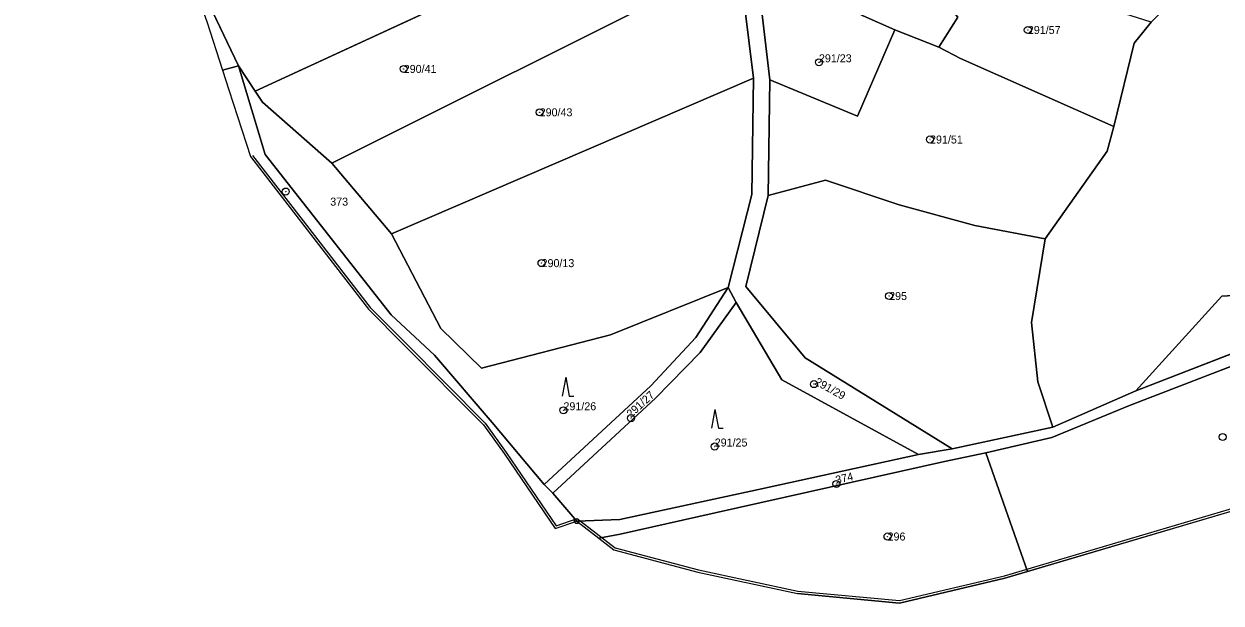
# Model space of a CAD drawing. Extents: x -652854 to -650068, y -1097661 to -1095417.
# Drawn here: x -652329 to -652074.7, y -1097660.5 to -1097537.5 of the extents above; entities that cross this region are included whole.
import ezdxf

# ---------------------------------------------------------------- set-up
doc = ezdxf.new("R2010")
doc.units = 0
for name, color, linetype in [('Definiční body parcel', 7, 'Continuous'), ('Geodetické body', 7, 'Continuous'), ('Hranice obcí', 7, 'Continuous'), ('Hranice parcel', 7, 'Continuous'), ('Obvody jako plochy', 7, 'Continuous'), ('Ostatní hranice', 7, 'Continuous'), ('Parcelní čísla', 7, 'Continuous'), ('Prvky pro prodl_ par_ č_', 7, 'Continuous'), ('Značky kultur', 7, 'Continuous')]:
    doc.layers.add(name, color=color, linetype=linetype)

msp = doc.modelspace()

# ---------------------------------------------------------------- linework, layer by layer
at = {"layer": 'Definiční body parcel'}
for centre, radius in [((-652115.77, -1097538.76), 0.75), ((-652115.77, -1097538.76), 0.0327), ((-652160.15, -1097545.62), 0.75), ((-652248.35, -1097547.03), 0.75), ((-652248.35, -1097547.03), 0.0327), ((-652160.15, -1097545.62), 0.0327), ((-652219.47, -1097556.25), 0.75), ((-652219.47, -1097556.25), 0.0327), ((-652136.55, -1097562.03), 0.75), ((-652136.55, -1097562.03), 0.0327), ((-652273.42, -1097573.09), 0.75), ((-652273.42, -1097573.09), 0.0327), ((-652219.07, -1097588.3), 0.75), ((-652219.07, -1097588.3), 0.0327), ((-652145.24, -1097595.29), 0.75), ((-652145.24, -1097595.29), 0.0327), ((-652161.2, -1097614.01), 0.75), ((-652161.2, -1097614.01), 0.0327), ((-652214.42, -1097619.57), 0.75), ((-652214.42, -1097619.57), 0.0327), ((-652200.08, -1097621.25), 0.75), ((-652200.08, -1097621.25), 0.0327), ((-652182.29, -1097627.27), 0.75), ((-652074.37, -1097625.25), 0.75), ((-652182.29, -1097627.27), 0.0327), ((-652156.43, -1097635.23), 0.75), ((-652156.43, -1097635.23), 0.0327), ((-652145.57, -1097646.4), 0.75), ((-652145.57, -1097646.4), 0.0327)]:
    msp.add_circle(centre, radius, dxfattribs=at)
at = {"layer": 'Geodetické body'}
for radius in [0.5, 0.5, 0.001, 0.001]:
    msp.add_circle((-652211.59, -1097643.14), radius, dxfattribs=at)
at = {"layer": 'Hranice obcí'}
for p, q in [((-652290.21, -1097536.96), (-652286.85, -1097547.32)), ((-652286.85, -1097547.32), (-652285.5, -1097551.5)), ((-652285.5, -1097551.5), (-652280.91, -1097565.66)), ((-652280.91, -1097565.66), (-652270.59, -1097579)), ((-652270.59, -1097579), (-652255.82, -1097598.11)), ((-652255.82, -1097598.11), (-652248.32, -1097605.66)), ((-652248.32, -1097605.66), (-652231.39, -1097622.64)), ((-652231.39, -1097622.64), (-652227.04, -1097628.79)), ((-652227.04, -1097628.79), (-652216.17, -1097644.7)), ((-652068.98, -1097639.97), (-652115.83, -1097653.84)), ((-652216.17, -1097644.7), (-652211.59, -1097643.14)), ((-652211.59, -1097643.14), (-652206.89, -1097646.75)), ((-652206.89, -1097646.75), (-652203.69, -1097649.21)), ((-652203.69, -1097649.21), (-652185.88, -1097653.98)), ((-652185.88, -1097653.98), (-652164.72, -1097658.5)), ((-652115.83, -1097653.84), (-652120.65, -1097655.27)), ((-652120.65, -1097655.27), (-652143.02, -1097660.54)), ((-652143.02, -1097660.54), (-652164.72, -1097658.5))]:
    msp.add_line(p, q, dxfattribs=at)
at = {"layer": 'Hranice parcel'}
for p, q in [((-652279.94, -1097551.79), (-652204.5, -1097516.92)), ((-652170.6, -1097549.34), (-652173.3, -1097526.39)), ((-652291.42, -1097529.59), (-652283.48, -1097546.39)), ((-652263.63, -1097567.04), (-652185.84, -1097528.13)), ((-652174.04, -1097549.02), (-652175.87, -1097534.12)), ((-652150.74, -1097535.77), (-652144.02, -1097538.72)), ((-652134.69, -1097542.44), (-652130.63, -1097536.04)), ((-652089.55, -1097537.12), (-652093.22, -1097541.53)), ((-652144.02, -1097538.72), (-652151.99, -1097557.1)), ((-652134.69, -1097542.44), (-652144.02, -1097538.72)), ((-652130.11, -1097544.83), (-652134.69, -1097542.44)), ((-652093.22, -1097541.53), (-652097.54, -1097559.24)), ((-652130.11, -1097544.83), (-652097.54, -1097559.24)), ((-652283.48, -1097546.39), (-652286.85, -1097547.32)), ((-652283.48, -1097546.39), (-652279.94, -1097551.79)), ((-652283.48, -1097546.39), (-652277.8, -1097565.24)), ((-652250.97, -1097582.05), (-652174.04, -1097549.02)), ((-652174.43, -1097573.73), (-652174.04, -1097549.02)), ((-652170.97, -1097573.93), (-652170.6, -1097549.34)), ((-652151.99, -1097557.1), (-652170.6, -1097549.34)), ((-652279.94, -1097551.79), (-652278.34, -1097554.07)), ((-652278.34, -1097554.07), (-652263.63, -1097567.04)), ((-652097.54, -1097559.24), (-652098.91, -1097564.48)), ((-652277.8, -1097565.24), (-652250.99, -1097599.3)), ((-652098.91, -1097564.48), (-652112.08, -1097583.17)), ((-652263.63, -1097567.04), (-652250.97, -1097582.05)), ((-652158.73, -1097570.67), (-652170.97, -1097573.93)), ((-652143.09, -1097575.93), (-652158.73, -1097570.67)), ((-652179.45, -1097593.46), (-652174.43, -1097573.73)), ((-652175.68, -1097593.25), (-652170.97, -1097573.93)), ((-652127.02, -1097580.3), (-652143.09, -1097575.93)), ((-652112.08, -1097583.17), (-652127.02, -1097580.3)), ((-652250.97, -1097582.05), (-652240.47, -1097602.17)), ((-652112.08, -1097583.17), (-652115.03, -1097600.94)), ((-652204.44, -1097603.55), (-652179.45, -1097593.46)), ((-652186.3, -1097604.08), (-652179.45, -1097593.46)), ((-652179.45, -1097593.46), (-652177.7, -1097596.65)), ((-652163.08, -1097608.43), (-652175.68, -1097593.25)), ((-652092.81, -1097615.42), (-652039.97, -1097594.93)), ((-652074.54, -1097595.34), (-652092.81, -1097615.42)), ((-652177.7, -1097596.65), (-652185.36, -1097607.28)), ((-652177.7, -1097596.65), (-652168.02, -1097613.07)), ((-652250.99, -1097599.3), (-652241.82, -1097607.85)), ((-652115.03, -1097600.94), (-652113.67, -1097613.52)), ((-652240.47, -1097602.17), (-652231.81, -1097610.6)), ((-652231.81, -1097610.6), (-652204.44, -1097603.55)), ((-652195.85, -1097614.41), (-652186.3, -1097604.08)), ((-652241.82, -1097607.85), (-652229.56, -1097622.15)), ((-652185.36, -1097607.28), (-652194.9, -1097616.98)), ((-652131.82, -1097627.74), (-652163.08, -1097608.43)), ((-652066.62, -1097607.96), (-652094.18, -1097618.53)), ((-652168.02, -1097613.07), (-652139.02, -1097628.97)), ((-652113.67, -1097613.52), (-652110.43, -1097623.16)), ((-652218.55, -1097635.33), (-652195.85, -1097614.41)), ((-652110.43, -1097623.16), (-652092.81, -1097615.42)), ((-652194.9, -1097616.98), (-652216.67, -1097637.21)), ((-652094.18, -1097618.53), (-652110.68, -1097625.36)), ((-652229.56, -1097622.15), (-652218.55, -1097635.33)), ((-652131.82, -1097627.74), (-652110.43, -1097623.16)), ((-652110.68, -1097625.36), (-652124.7, -1097628.63)), ((-652172.99, -1097636.38), (-652139.02, -1097628.97)), ((-652139.02, -1097628.97), (-652131.82, -1097627.74)), ((-652124.7, -1097628.63), (-652133.45, -1097630.46)), ((-652124.7, -1097628.63), (-652115.83, -1097653.84)), ((-652133.45, -1097630.46), (-652182.16, -1097641.4)), ((-652218.55, -1097635.33), (-652216.67, -1097637.21)), ((-652202.46, -1097642.79), (-652172.99, -1097636.38)), ((-652216.67, -1097637.21), (-652211.59, -1097643.14)), ((-652182.16, -1097641.4), (-652202.36, -1097645.87)), ((-652211.59, -1097643.14), (-652202.46, -1097642.79)), ((-652202.36, -1097645.87), (-652206.89, -1097646.75))]:
    msp.add_line(p, q, dxfattribs=at)
at = {"layer": 'Obvody jako plochy'}
for points in [[(-652283.48, -1097546.39), (-652291.42, -1097529.59), (-652293.53, -1097523.16), (-652302.62, -1097501.1), (-652308.48, -1097486.7), (-652318.45, -1097463.12), (-652326.36, -1097443.74), (-652329.03, -1097442.14), (-652325.62, -1097450.58), (-652313.01, -1097480.64), (-652302.46, -1097506.84), (-652293.93, -1097526.58), (-652290.21, -1097536.96), (-652286.85, -1097547.32)], [(-652231, -1097501.01), (-652291.42, -1097529.59), (-652283.48, -1097546.39), (-652279.94, -1097551.79), (-652204.5, -1097516.92)], [(-652110.43, -1097623.16), (-652092.81, -1097615.42), (-652074.54, -1097595.34), (-652054.54, -1097594.13), (-652025.66, -1097577.57), (-652014.27, -1097557.8), (-652016.26, -1097555.47), (-652054.38, -1097506.4), (-652060.34, -1097499.52), (-652065.98, -1097508.03), (-652074.75, -1097521.21), (-652081.84, -1097529.25), (-652089.55, -1097537.12), (-652093.22, -1097541.53), (-652097.54, -1097559.24), (-652098.91, -1097564.48), (-652112.08, -1097583.17), (-652115.03, -1097600.94), (-652113.67, -1097613.52)], [(-652204.5, -1097516.92), (-652279.94, -1097551.79), (-652278.34, -1097554.07), (-652263.63, -1097567.04), (-652185.84, -1097528.13)], [(-652150.74, -1097535.77), (-652144.02, -1097538.72), (-652134.69, -1097542.44), (-652130.63, -1097536.04), (-652145.51, -1097518.48), (-652149.63, -1097517.12), (-652158.81, -1097530.29)], [(-652089.55, -1097537.12), (-652119.6, -1097527.55), (-652145.51, -1097518.48), (-652130.63, -1097536.04), (-652134.69, -1097542.44), (-652130.11, -1097544.83), (-652097.54, -1097559.24), (-652093.22, -1097541.53)], [(-652177.7, -1097596.65), (-652168.02, -1097613.07), (-652139.02, -1097628.97), (-652131.82, -1097627.74), (-652163.08, -1097608.43), (-652175.68, -1097593.25), (-652170.97, -1097573.93), (-652170.6, -1097549.34), (-652173.3, -1097526.39), (-652176.77, -1097526.81), (-652175.87, -1097534.12), (-652174.04, -1097549.02), (-652174.43, -1097573.73), (-652179.45, -1097593.46)], [(-652144.02, -1097538.72), (-652150.74, -1097535.77), (-652173.3, -1097526.39), (-652170.6, -1097549.34), (-652151.99, -1097557.1)], [(-652174.04, -1097549.02), (-652175.87, -1097534.12), (-652185.84, -1097528.13), (-652263.63, -1097567.04), (-652250.97, -1097582.05)], [(-652144.02, -1097538.72), (-652151.99, -1097557.1), (-652170.6, -1097549.34), (-652170.97, -1097573.93), (-652158.73, -1097570.67), (-652143.09, -1097575.93), (-652127.02, -1097580.3), (-652112.08, -1097583.17), (-652098.91, -1097564.48), (-652097.54, -1097559.24), (-652130.11, -1097544.83), (-652134.69, -1097542.44)], [(-652229.56, -1097622.15), (-652241.82, -1097607.85), (-652250.99, -1097599.3), (-652277.8, -1097565.24), (-652283.48, -1097546.39), (-652286.85, -1097547.32), (-652285.5, -1097551.5), (-652280.91, -1097565.66), (-652270.59, -1097579), (-652255.82, -1097598.11), (-652248.32, -1097605.66), (-652231.39, -1097622.64), (-652227.04, -1097628.79), (-652216.17, -1097644.7), (-652211.59, -1097643.14), (-652216.67, -1097637.21), (-652218.55, -1097635.33)], [(-652229.56, -1097622.15), (-652218.55, -1097635.33), (-652195.85, -1097614.41), (-652186.3, -1097604.08), (-652179.45, -1097593.46), (-652204.44, -1097603.55), (-652231.81, -1097610.6), (-652240.47, -1097602.17), (-652250.97, -1097582.05), (-652263.63, -1097567.04), (-652278.34, -1097554.07), (-652279.94, -1097551.79), (-652283.48, -1097546.39), (-652277.8, -1097565.24), (-652250.99, -1097599.3), (-652241.82, -1097607.85)], [(-652231.81, -1097610.6), (-652204.44, -1097603.55), (-652179.45, -1097593.46), (-652174.43, -1097573.73), (-652174.04, -1097549.02), (-652250.97, -1097582.05), (-652240.47, -1097602.17)], [(-651973.77, -1097554.49), (-652002.3, -1097573.25), (-652016.98, -1097582.72), (-652039.97, -1097594.93), (-652092.81, -1097615.42), (-652110.43, -1097623.16), (-652131.82, -1097627.74), (-652139.02, -1097628.97), (-652172.99, -1097636.38), (-652202.46, -1097642.79), (-652211.59, -1097643.14), (-652206.89, -1097646.75), (-652202.36, -1097645.87), (-652182.16, -1097641.4), (-652133.45, -1097630.46), (-652124.7, -1097628.63), (-652110.68, -1097625.36), (-652094.18, -1097618.53), (-652066.62, -1097607.96), (-652039.56, -1097597.62), (-652015, -1097585.11), (-651982.42, -1097563.86), (-651971.9, -1097556.17), (-651973.16, -1097555.12)], [(-651971.9, -1097556.17), (-651982.42, -1097563.86), (-652015, -1097585.11), (-652039.56, -1097597.62), (-652066.62, -1097607.96), (-652094.18, -1097618.53), (-652110.68, -1097625.36), (-652124.7, -1097628.63), (-652115.83, -1097653.84), (-652068.98, -1097639.97), (-652062.89, -1097636.13), (-652056.48, -1097632.08), (-652034.17, -1097618.79), (-652008.05, -1097598.16), (-651979.45, -1097565.25)], [(-652092.81, -1097615.42), (-652039.97, -1097594.93), (-652016.98, -1097582.72), (-652002.3, -1097573.25), (-652010.6, -1097562.44), (-652014.27, -1097557.8), (-652025.66, -1097577.57), (-652054.54, -1097594.13), (-652074.54, -1097595.34)], [(-652131.82, -1097627.74), (-652110.43, -1097623.16), (-652113.67, -1097613.52), (-652115.03, -1097600.94), (-652112.08, -1097583.17), (-652127.02, -1097580.3), (-652143.09, -1097575.93), (-652158.73, -1097570.67), (-652170.97, -1097573.93), (-652175.68, -1097593.25), (-652163.08, -1097608.43)], [(-652218.55, -1097635.33), (-652216.67, -1097637.21), (-652194.9, -1097616.98), (-652185.36, -1097607.28), (-652177.7, -1097596.65), (-652179.45, -1097593.46), (-652186.3, -1097604.08), (-652195.85, -1097614.41)], [(-652216.67, -1097637.21), (-652211.59, -1097643.14), (-652202.46, -1097642.79), (-652172.99, -1097636.38), (-652139.02, -1097628.97), (-652168.02, -1097613.07), (-652177.7, -1097596.65), (-652185.36, -1097607.28), (-652194.9, -1097616.98)], [(-652133.45, -1097630.46), (-652182.16, -1097641.4), (-652202.36, -1097645.87), (-652206.89, -1097646.75), (-652203.69, -1097649.21), (-652185.88, -1097653.98), (-652164.72, -1097658.5), (-652143.02, -1097660.54), (-652120.65, -1097655.27), (-652115.83, -1097653.84), (-652124.7, -1097628.63)]]:
    msp.add_lwpolyline(points, close=True, dxfattribs=at)
at = {"layer": 'Ostatní hranice'}
for p, q in [((-652280.45, -1097565.45), (-652270.18, -1097578.69)), ((-652270.18, -1097578.69), (-652255.45, -1097597.76)), ((-652255.45, -1097597.76), (-652248, -1097605.27)), ((-652248, -1097605.27), (-652231.03, -1097622.28)), ((-652231.03, -1097622.28), (-652226.58, -1097628.56)), ((-652226.58, -1097628.56), (-652215.96, -1097644.11)), ((-652120.75, -1097654.77), (-652069.1, -1097639.48)), ((-652215.96, -1097644.11), (-652211.5, -1097642.57)), ((-652211.5, -1097642.57), (-652203.44, -1097648.77)), ((-652203.44, -1097648.77), (-652185.76, -1097653.49)), ((-652185.76, -1097653.49), (-652164.66, -1097657.99)), ((-652143.02, -1097660.03), (-652120.75, -1097654.77)), ((-652164.66, -1097657.99), (-652143.02, -1097660.03))]:
    msp.add_line(p, q, dxfattribs=at)
at = {"layer": 'Značky kultur'}
for p, q in [((-652213.942, -1097612.559), (-652214.675, -1097616.559)), ((-652213.942, -1097612.559), (-652213.209, -1097616.559)), ((-652213.209, -1097616.559), (-652212.209, -1097616.559)), ((-652182.252, -1097619.389), (-652182.985, -1097623.389)), ((-652182.252, -1097619.389), (-652181.519, -1097623.389)), ((-652181.519, -1097623.389), (-652180.519, -1097623.389))]:
    msp.add_line(p, q, dxfattribs=at)

# ---------------------------------------------------------------- texts
at = {"layer": 'Parcelní čísla'}
for s, height, p in [('291/57', 1.7, (-652115.77, -1097539.61)), ('291/23', 1.7, (-652160.15, -1097545.62)), ('290/41', 1.7, (-652248.35, -1097547.88)), ('290/43', 1.7, (-652219.47, -1097557.1)), ('291/51', 1.7, (-652136.55, -1097562.88)), ('373', 0.1, (-652273.42, -1097573.09)), ('290/13', 1.7, (-652219.07, -1097589.15)), ('295', 1.7, (-652145.24, -1097596.14)), ('291/26', 1.7, (-652214.42, -1097619.57)), ('291/25', 1.7, (-652182.29, -1097627.27)), ('296', 1.7, (-652145.57, -1097647.25))]:
    msp.add_text(s, height=height, dxfattribs=at).set_placement(p)
for s, rotation, p in [('291/29', 330.831, (-652161.2, -1097614.01)), ('291/27', 42.219, (-652200.08, -1097621.25)), ('374', 12.744, (-652156.43, -1097635.23))]:
    msp.add_text(s, height=1.7, rotation=rotation, dxfattribs=at).set_placement(p)
at = {"layer": 'Prvky pro prodl_ par_ č_'}
msp.add_text('373', height=1.7, dxfattribs=at).set_placement((-652263.96, -1097576.08))

doc.saveas('drawing.dxf')
